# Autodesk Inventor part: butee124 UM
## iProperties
Author: Administrateur
Created: 2002-02
Part Number: butee124 UM
Material: Par défaut
Document SubType Name: Modélisation
Designer: Administrateur
Control State: 0
Master: False
Checked Out: False
PropertySet Name: Design Tracking Control
Shininess: 20.0
Angle Display Precision: 2
Document Length Units: 11269
Document Angle Units: 11283
Document Time Units: 11279
Document Mass Units: 11290
Document Length Units Precision: 3
Document Angle Units Precision: 2
Compacted: False
PropertySet Name: _Private Model Information
Density: 0.0
Volumn: 0.0
Area: 0.0
PropertySet Name: Model Information
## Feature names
1. Extrusion1
2. Perçage1 [Hole]
3. Extrusion2
